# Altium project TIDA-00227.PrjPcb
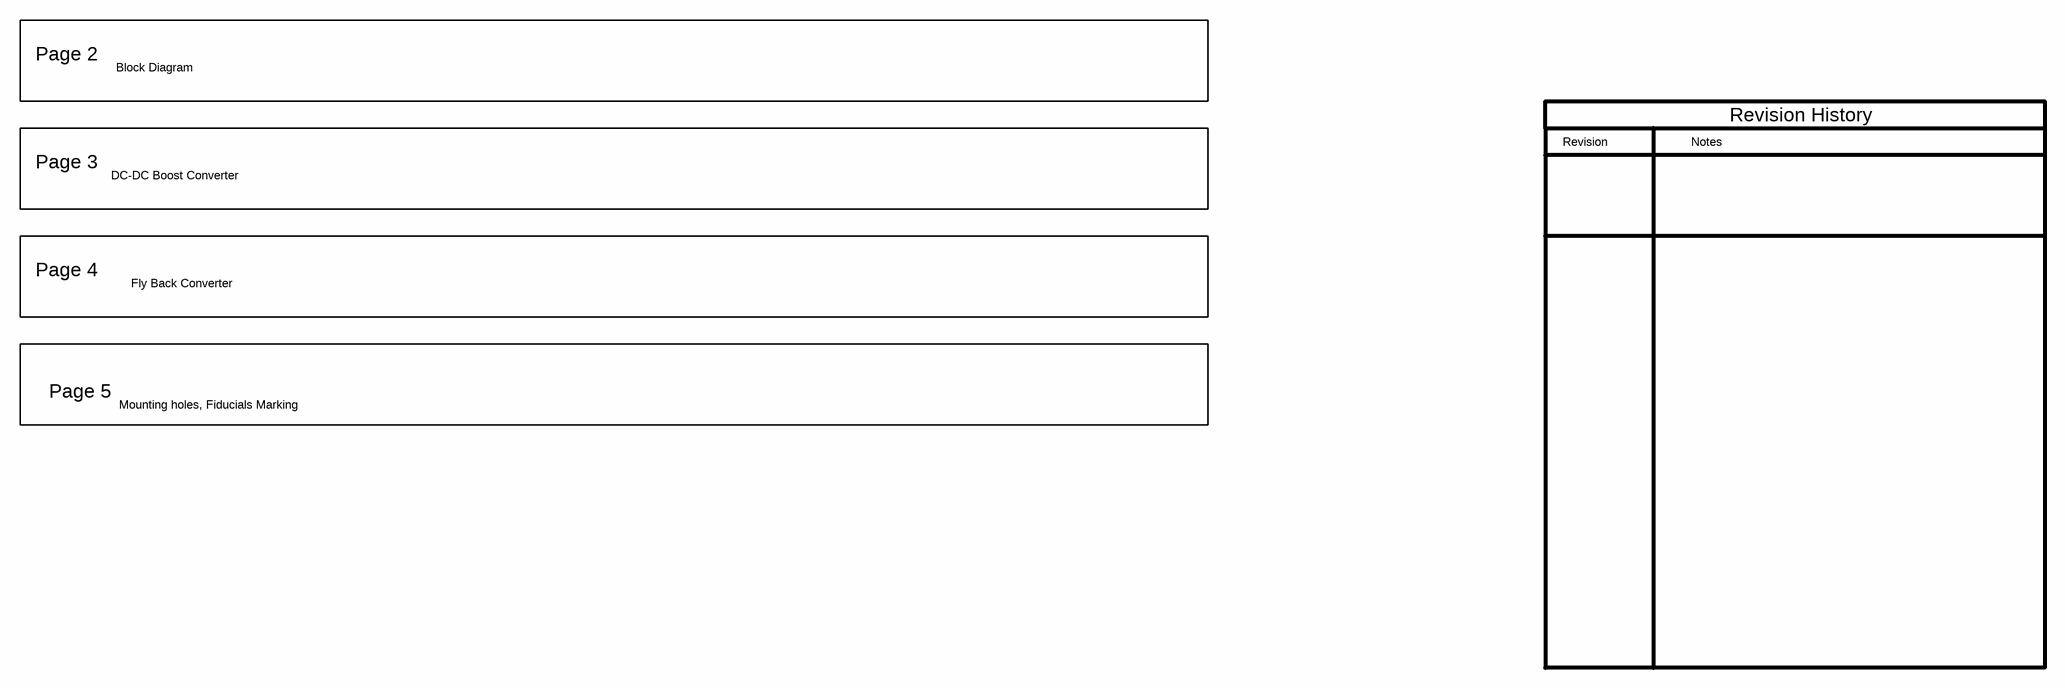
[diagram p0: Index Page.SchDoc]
CopyrightYear: 2014; PCB_Rev: A1; PRJ_Customer: Public Release; PRJ_Engineer: Sunil Dwivedi; PRJ_Number: TIDA-00227; PRJ_Title: TIDA-00227 - ISE3033; SCH_Rev: A1; TechSupport: http://www.ti.com/support
5 sheets, 146 parts. Net scope: flat (ports and power ports of the same name join across sheets).
Board file: TIDA-00227.PcbDoc
Sheets:
  Index Page.SchDoc
  Block Diagram.SchDoc
  Boost converter.SchDoc
  Fly back converter.SchDoc
  Hardware.SchDoc

## Sheet Index Page.SchDoc: Index Page
size 431 x 279 mm; Date: Not shown in title block; ApprovedBy: Not shown in title block; CheckedBy: Not shown in title block; Author: Not shown in title block; CompanyName: Not shown in title block; Engineer: Not shown in title block; Organization: Not shown in title block; Address1: Not shown in title block; Address2: Not shown in title block; Address3: Not shown in title block; Address4: Not shown in title block; DocumentNumber: 1; Revision: Use project parameter SCH_Rev; SheetNumber: 1; SheetTotal: 5; PageSetup: Record=PageOptions|CenterHorizontal=True|CenterVertical=True|PrintScale=1.00|XCorrection=1.00|YCorrection=1.00|PrintKind=0|BorderSize=5000000|LeftOffset=0|BottomOffset=0|Orientation=2|PaperLength=1000|PaperWidth=1000|Scale=100|PaperSource=15|PrintQuality=600|MediaType=1|DitherType=10|PaperKind=Letter|PrintScaleMode=1

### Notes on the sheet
- Page 2
- Block Diagram
- Page 3
- Revision
- Notes
- Revision History
- DC-DC Boost Converter
- Page 4
- Fly Back Converter
- Page 5
- Mounting holes, Fiducials Marking

## Sheet Block Diagram.SchDoc: Block Diagram
size 431 x 279 mm; Date: Not shown in title block; ApprovedBy: Not shown in title block; CheckedBy: Not shown in title block; Author: Not shown in title block; CompanyName: Not shown in title block; Engineer: Not shown in title block; Organization: Not shown in title block; Address1: Not shown in title block; Address2: Not shown in title block; Address3: Not shown in title block; Address4: Not shown in title block; DocumentNumber: 2; Revision: Use project parameter SCH_Rev; SheetNumber: 2; SheetTotal: 5; PageSetup: Record=PageOptions|CenterHorizontal=True|CenterVertical=True|PrintScale=0.96|XCorrection=1.00|YCorrection=1.00|PrintKind=0|BorderSize=5000000|LeftOffset=0|BottomOffset=0|Orientation=2|PaperLength=1000|PaperWidth=1000|Scale=100|PaperSource=15|PrintQuality=600|MediaType=1|DitherType=10|PaperKind=A3|PrintScaleMode=1
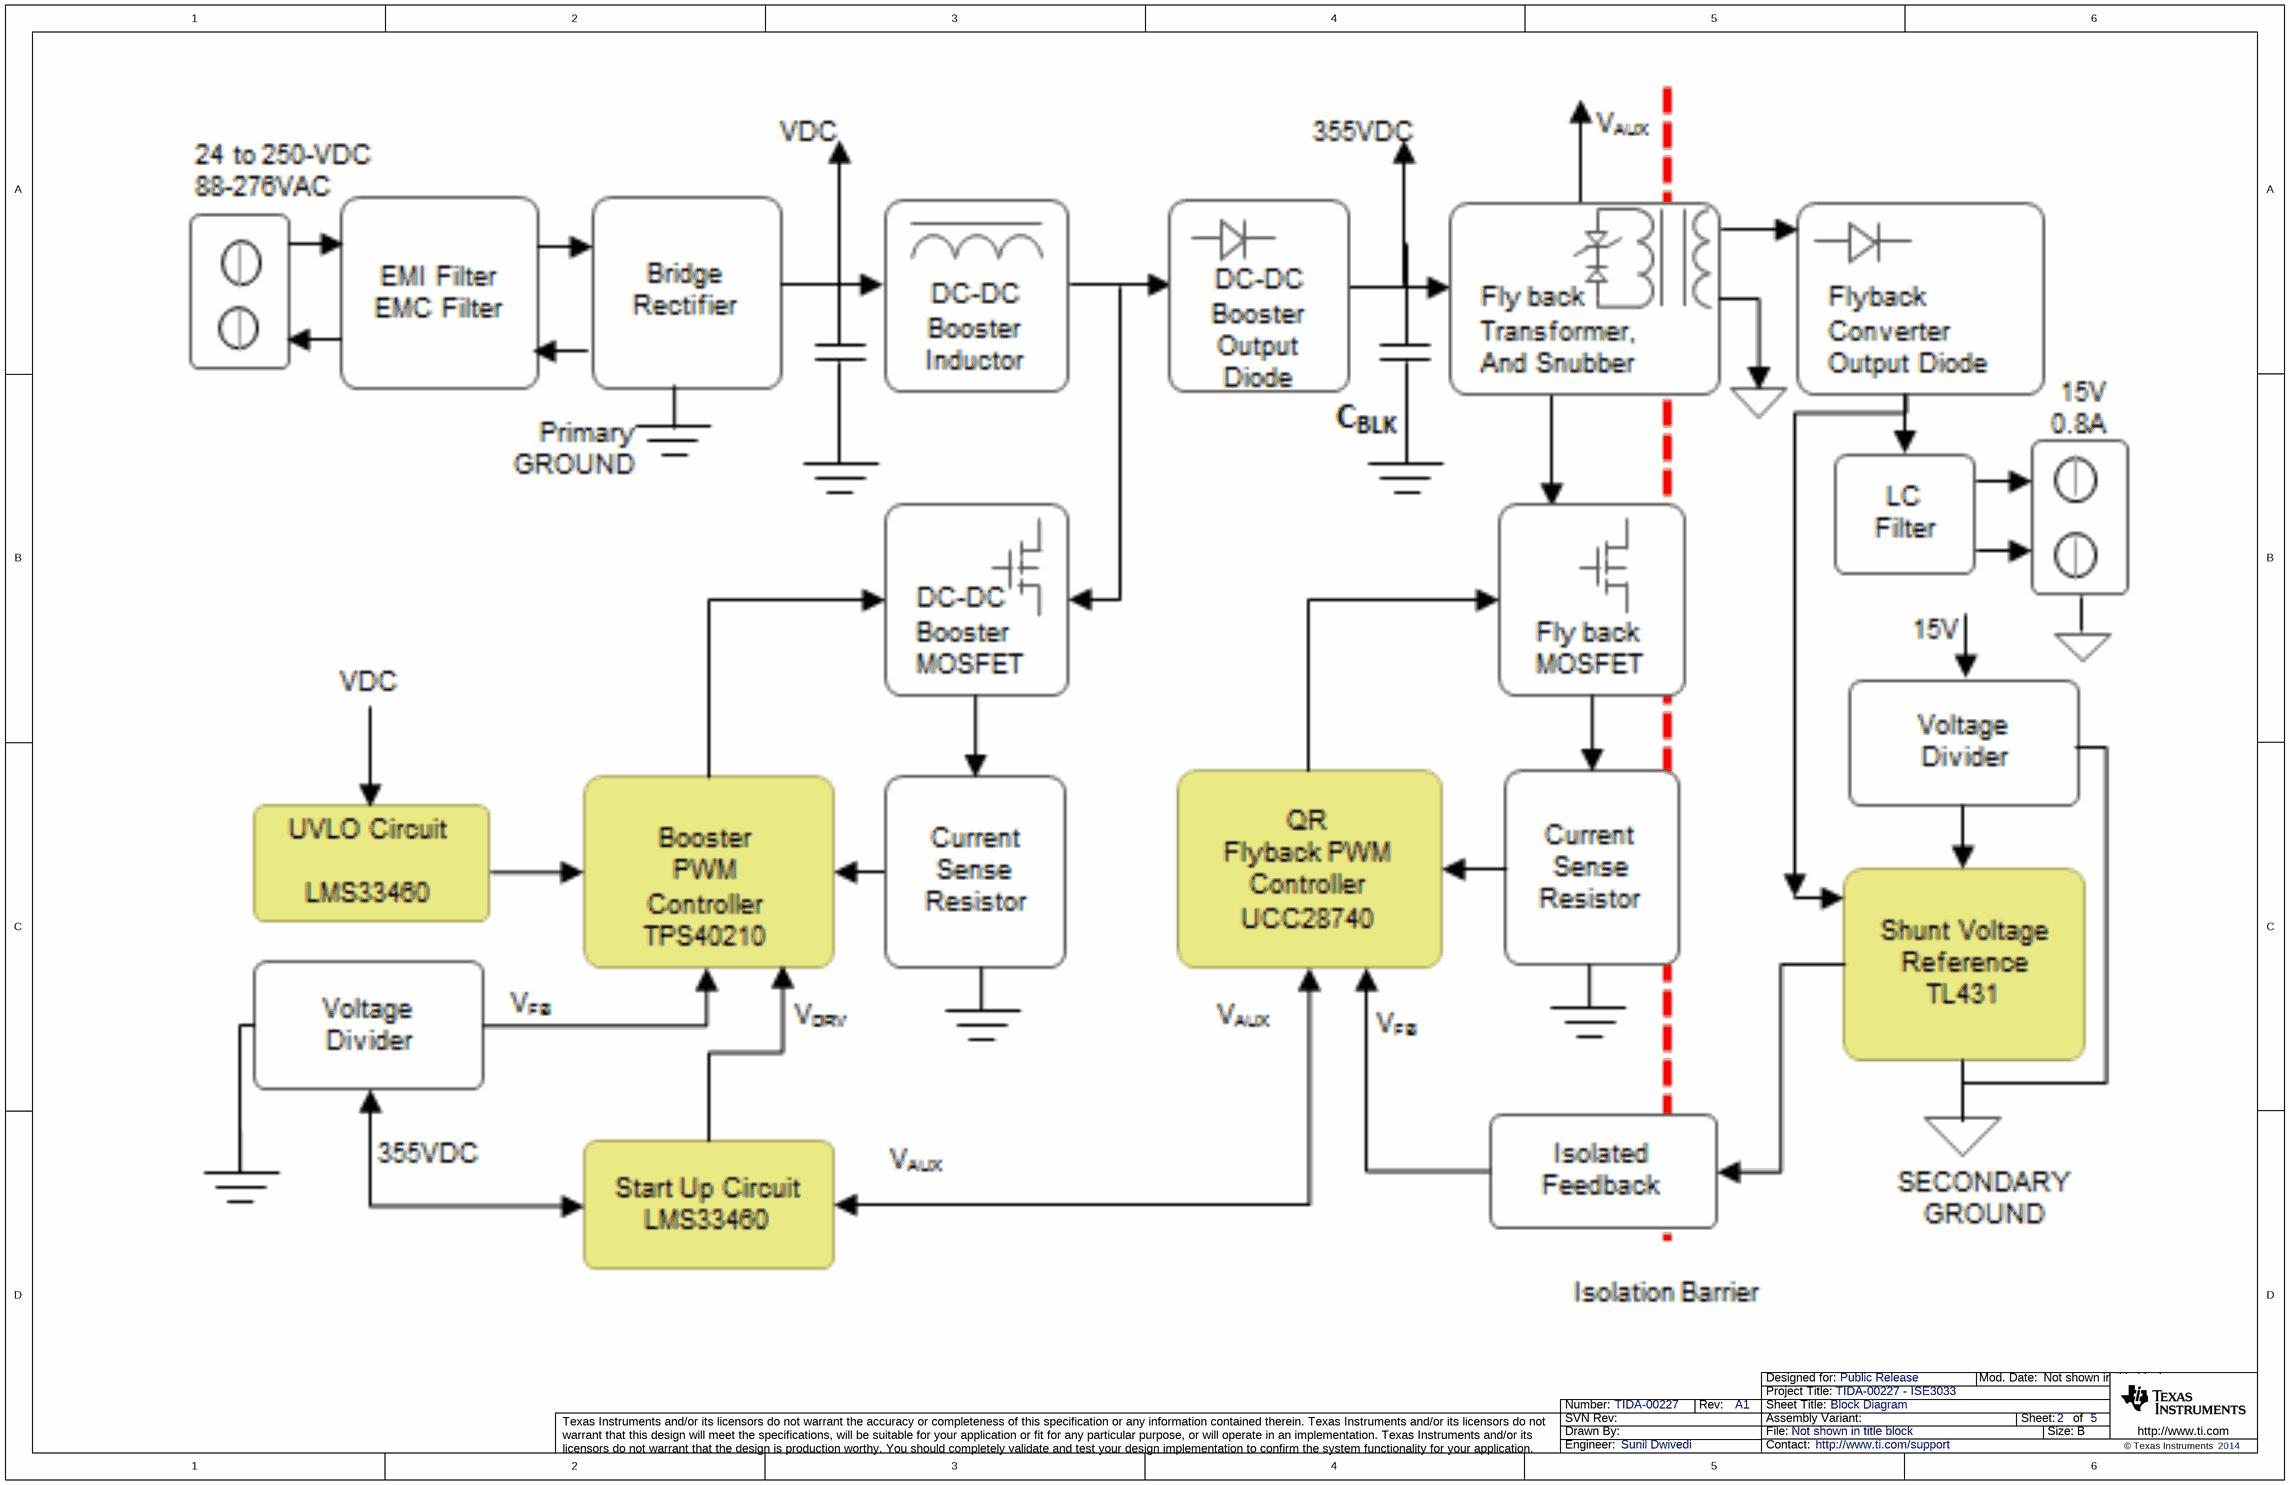
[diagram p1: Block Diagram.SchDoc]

## Sheet Boost converter.SchDoc: DC-DC Boost Converter
size 431 x 279 mm; Date: Not shown in title block; ApprovedBy: Not shown in title block; CheckedBy: Not shown in title block; Author: Not shown in title block; CompanyName: Not shown in title block; Engineer: Not shown in title block; Organization: Not shown in title block; Address1: Not shown in title block; Address2: Not shown in title block; Address3: Not shown in title block; Address4: Not shown in title block; DocumentNumber: 3; Revision: Use project parameter SCH_Rev; SheetNumber: 3; SheetTotal: 5; PageSetup: Record=PageOptions|CenterHorizontal=True|CenterVertical=True|PrintScale=1.00|XCorrection=1.00|YCorrection=1.00|PrintKind=0|BorderSize=5000000|LeftOffset=0|BottomOffset=0|Orientation=2|PaperLength=1000|PaperWidth=1000|Scale=100|PaperSource=15|PrintQuality=600|MediaType=1|DitherType=10|PaperKind=Letter|PrintScaleMode=1
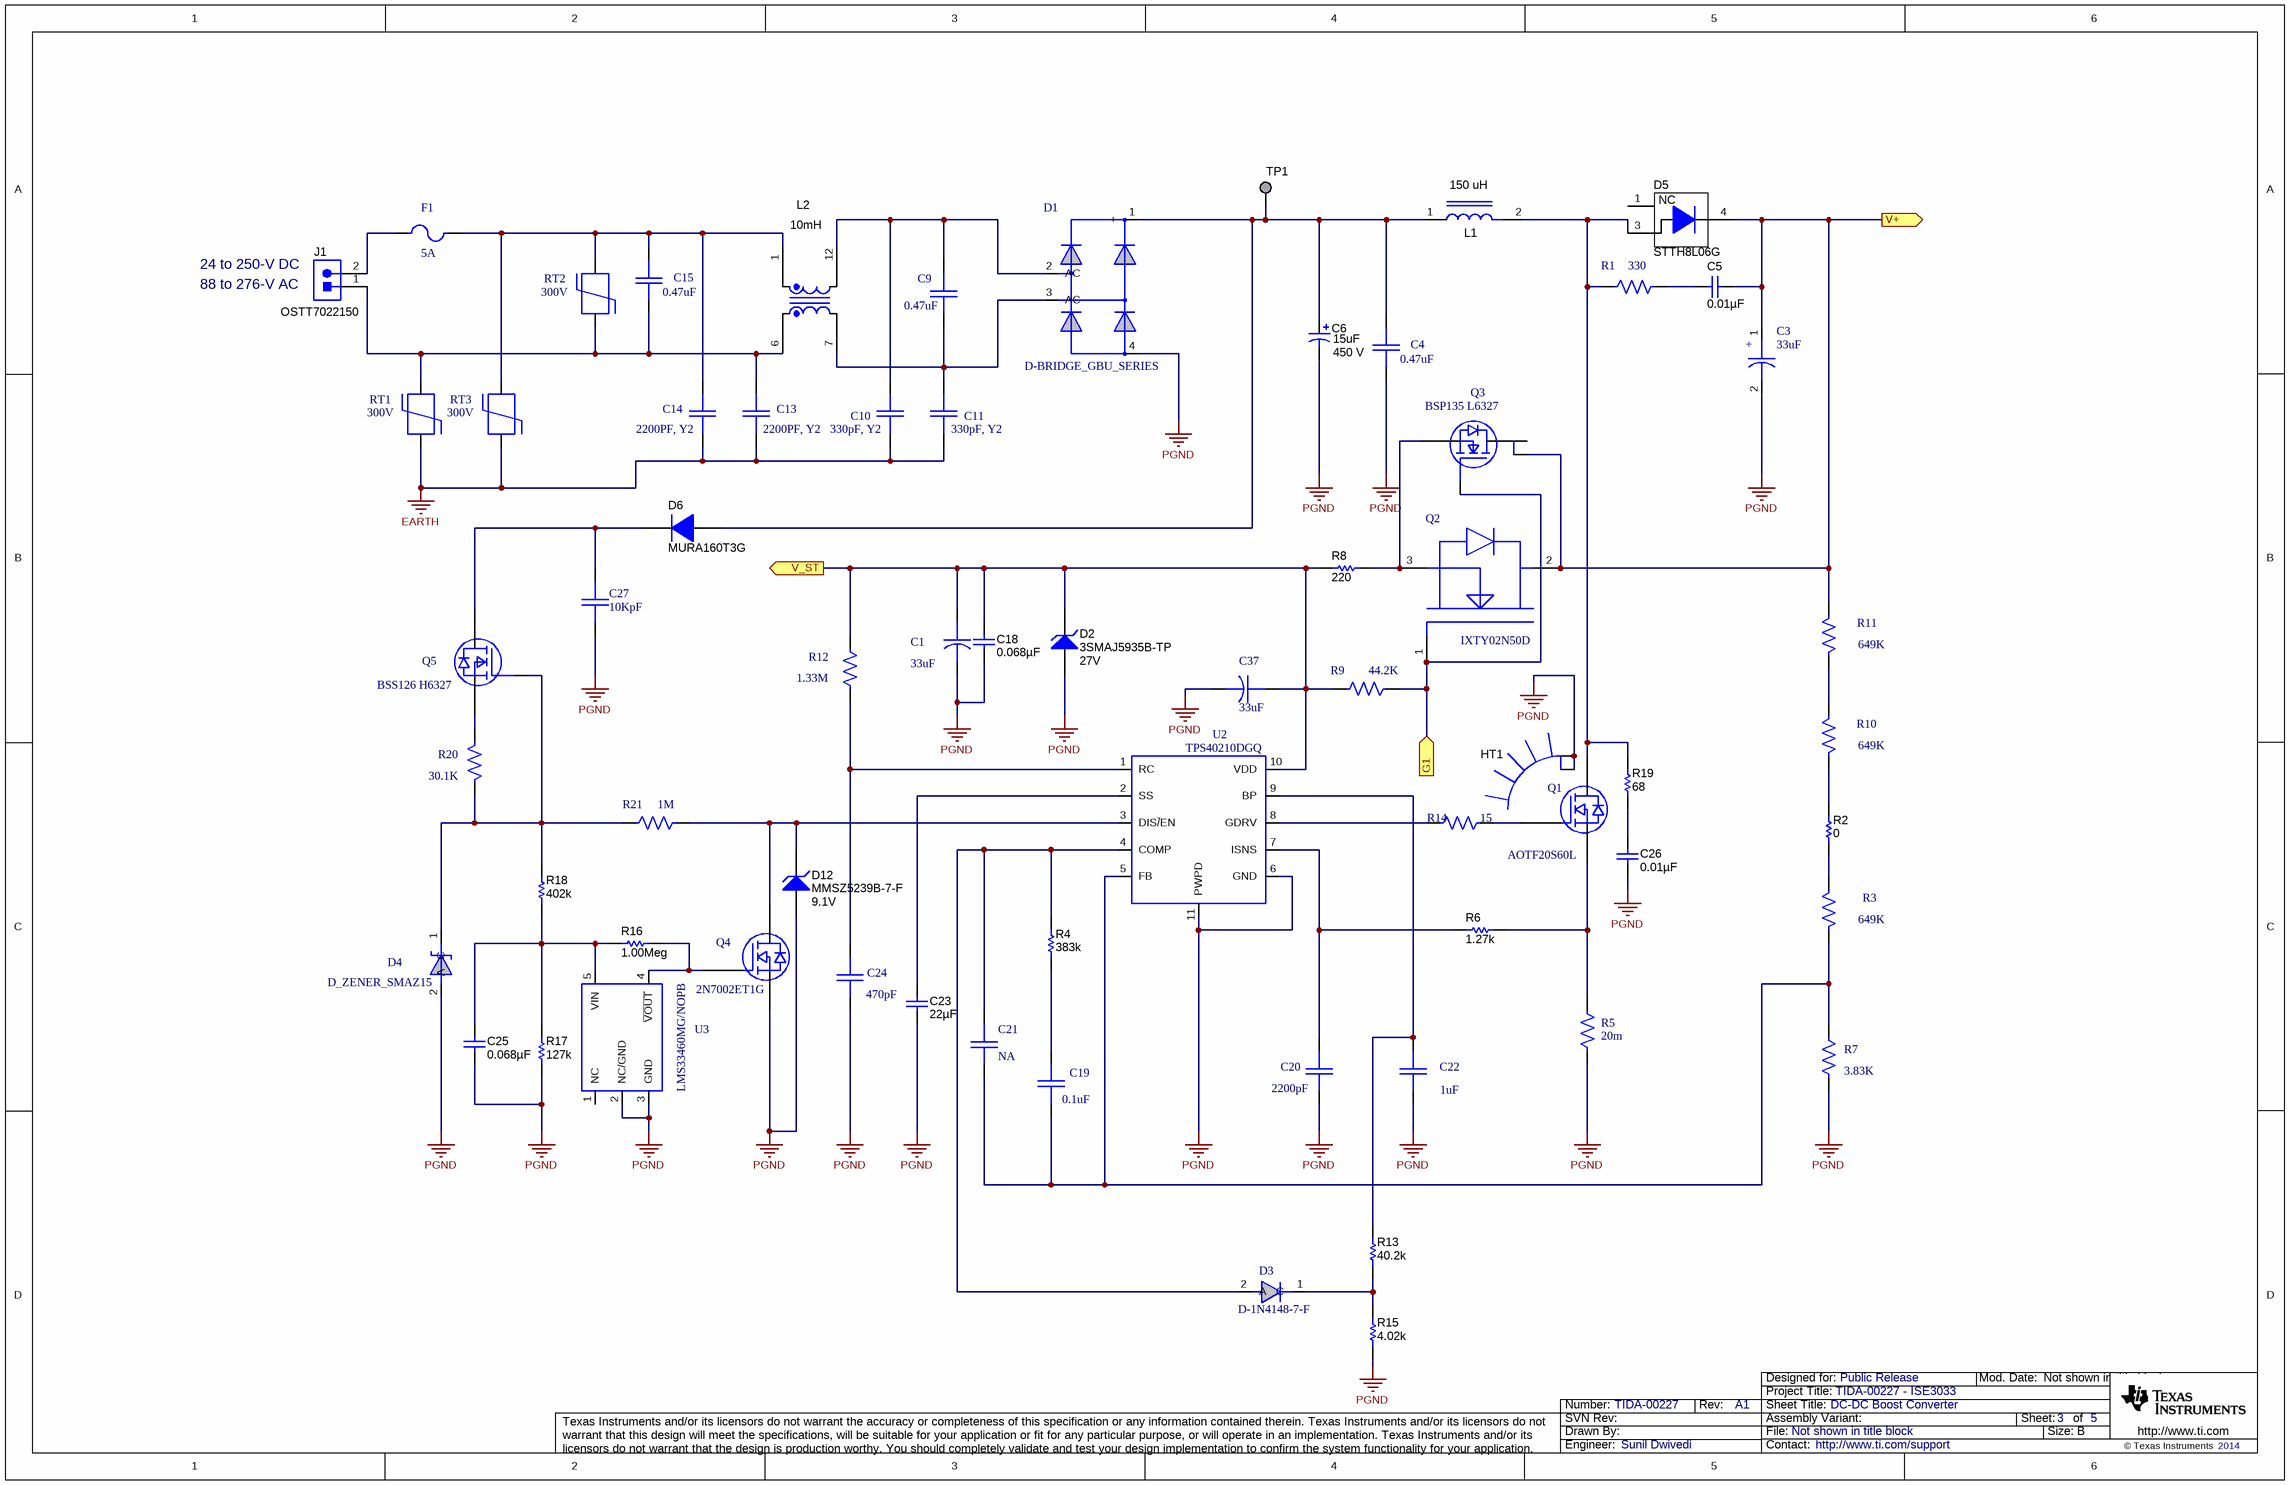
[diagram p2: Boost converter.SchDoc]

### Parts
C1  value 33uF  [CAP_ZL-6.3MM]  (hidden comment: CAP_ZL_6.3MM_SERIES)
C3  33uF  [CAP_EEUFC1H]
C4  value 0.47uF  [CAP_591MIL]  (hidden comment: R46KI347050P1M)
C5  ValueDisplayed: 0.01µF  [1210]  (hidden comment: GRM32QR73A103KW01L)
C6  value 15uF  VDC_V: 450 V  [CAPPR5-12.5X20]  (hidden comment: EEU-EE2W150)
C9  value 0.47uF  [CAP_591MIL]  (hidden comment: R46KI347050P1M)
C10  value 330pF, Y2  [CAP_DISK_8.4MM]  (hidden comment: CAP_DISK_440_[8.4MM])
C11  value 330pF, Y2  [CAP_DISK_8.4MM]  (hidden comment: CAP_DISK_440_[8.4MM])
C13  value 2200PF, Y2  [CAP_DISK_8.4MM]  (hidden comment: VY2222M35Y5US63V7)
C14  value 2200PF, Y2  [CAP_DISK_8.4MM]  (hidden comment: VY2222M35Y5US63V7)
C15  value 0.47uF  [CAP_591MIL]  (hidden comment: R46KI347050P1M)
C18  ValueDisplayed: 0.068µF  [0603]  (hidden comment: GRM188R71H683KA93D)
C19  value 0.1uF  [C603]  (hidden comment: C603)
C20  value 2200pF  [C603]  (hidden comment: C603)
C21  value NA  [C603]  (hidden comment: C603)
C22  value 1uF  [C603]  (hidden comment: C603)
C23  ValueDisplayed: 22µF  [0805_HV]  (hidden comment: C2012X5R1C226K125AC)
C24  value 470pF  [C603]  (hidden comment: C603)
C25  ValueDisplayed: 0.068µF  [0603]  (hidden comment: GRM188R71H683KA93D)
C26  ValueDisplayed: 0.01µF  [1210]  (hidden comment: GRM32QR73A103KW01L)
C27  value 10KpF  [C1812]  (hidden comment: C4532CH2J103K160KA)
C37  value 33uF  [CAP_ZL-6.3MM]  (hidden comment: CAP_ZL_6.3MM_SERIES)
D1  D-BRIDGE_GBU_SERIES  [BRIDGE-INLINE-210-C]
D2  3SMAJ5935B-TP  value 27V  [SMA]
D3  D-1N4148-7-F  [D_SOD123]
D4  D_ZENER_SMAZ15  [DIODE_SMA]
D5  STTH8L06G  [DDPAK]
D6  MURA160T3G  [SMA]
D12  MMSZ5239B-7-F  value 9.1V  [SOD-123]
F1  value 5A  [FUSE_4X8.5-5.08P]  (hidden comment: FUSE_RST_SERIES)
HT1  HEATSINK_513102B02500G  [HEATSINK_513201]  (value not drawn)
J1  OSTT7022150  [TERM_BLK_OSTT7022150]
L1  150 uH  [IND_AIRD-06-151K]
L2  ValueDisplayed: 10mH  [WE-CMB_XL]  (hidden comment: 744825510)
Q1  value AOTF20S60L  [TO-220V]  (hidden comment: TR-FQPF2N60C)
Q2  IXTY02N50D  [TO228P991X238-3N]
Q3  value BSP135 L6327  [TR_SOT223]  (hidden comment: TR_NFET_SOT223)
Q4  value 2N7002ET1G  [SOT-23]  (hidden comment: TR-2N7002)
Q5  value BSS126 H6327  [SOT-23]  (hidden comment: TR-BSS126)
R1  value 330  [R2512]  (hidden comment: R2512)
R2  value 0  [1206]  (hidden comment: RC1206JR-070RL)
R3  value 649K  [r1206]  (hidden comment: R1206)
R4  value 383k  [0603]  (hidden comment: CRCW0603383KFKEA)
R5  value 20m  [R2512]  (hidden comment: R2512_1%)
R6  value 1.27k  [0603]  (hidden comment: CRCW06031K27FKEA)
R7  value 3.83K  [R603]  (hidden comment: R603)
R8  value 220  [0603]  (hidden comment: RC0603FR-07220RL)
R9  value 44.2K  [R603]  (hidden comment: R603)
R10  value 649K  [R1206]  (hidden comment: R1206)
R11  value 649K  [R1206]  (hidden comment: R1206)
R12  value 1.33M  [R603]  (hidden comment: R603)
R13  value 40.2k  [0603]  (hidden comment: CRCW060340K2FKEA)
R14  value 15  [R0805]  (hidden comment: R0805_1%)
R15  value 4.02k  [0603]  (hidden comment: RC0603FR-074K02L)
R16  value 1.00Meg  [0603]  (hidden comment: CRCW06031M00FKEA)
R17  value 127k  [0603]  (hidden comment: CRCW0603127KFKEA)
R18  value 402k  [0603]  (hidden comment: CRCW0603402KFKEA)
R19  value 68  [2512M]  (hidden comment: RHC2512FT68R0)
R20  value 30.1K  [R603]  (hidden comment: R603)
R21  value 1M  [R603]  (hidden comment: R603)
RT1  value 300V  [DISK-472]  (hidden comment: MOV_B72210SXXXXK101)
RT2  value 300V  [DISK-472]  (hidden comment: MOV_B72210SXXXXK101)
RT3  value 300V  [DISK-472]  (hidden comment: MOV_B72210SXXXXK101)
TP1  TESTPOINT  [TESTPOINT]  (value not drawn)  (no BOM)
U2  TPS40210DGQ  [DGQ_10PWP]
U3  value LMS33460MG/NOPB  [SC-70-5]  (hidden comment: LMS33460)

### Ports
G1, V+, V_ST

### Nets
EARTH: C10.2 C11.2 C13.2 C14.2 RT1.1 RT3.1
PGND: C1.2 C3.2 C4.1 C6.2(-) C18.2 C20.1 C22.1 C23.2 C24.1 C25.2 C26.2 C27.1 C37.2 D1.4(-) D2.2(A) D4.2(A) D12.2(A) HT1.1 HT1.2 Q4.2(S) R5.2 R7.2 R15.1 R17.2 U2.6(GND) U2.11(PWPD) U3.2(NC/GND) U3.3(GND)
NetC1_1: C1.1 C18.1 C37.1 D2.1(K) R8.1 R9.2 R12.1 U2.10(VDD) ; port V_ST
NetC2_2: C3.1 C5.2 D5.4(K) Q2.2(D) Q3.4(D) R11.1 ; port V+
NetC4_2: C4.2 C6.1(+) D1.1(+) D6.2(A) L1.1 TP1.1
NetC5_1: C5.1 R1.2
NetC9_1: C9.1 C11.1 D1.3(AC) L2.7
NetC9_2: C9.2 C10.1 D1.2(AC) L2.12
NetC13_1: C13.1 C15.1 J1.1 L2.6 RT1.2 RT2.1
NetC14_1: C14.1 C15.2 F1.2 L2.1 RT2.2 RT3.2
NetC19_1: C19.1 R4.2
NetC19_2: C19.2 C21.1 R3.2 R7.1 U2.5(FB)
NetC20_2: C20.2 R6.1 U2.7(ISNS)
NetC21_2: C21.2 D3.2(A) R4.1 U2.4(COMP)
NetC22_2: C22.2 R13.2 U2.9(BP)
NetC23_1: C23.1 U2.2(SS)
NetC24_2: C24.2 R12.2 U2.1(RC)
NetC25_1: C25.1 R16.1 R17.1 R18.2 U3.5(VIN)
NetC26_1: C26.1 R19.1
NetC27_2: C27.2 D6.1(K) Q5.3(D)
NetD3_1: D3.1(C) R13.1 R15.2
NetD4_1: D4.1(C) Q5.1(G) R18.1 R20.2 R21.1
NetD5_3: D5.3(A) L1.2 Q1.2(D) R1.1 R19.2
NetD12_1: D12.1(K) Q4.3(D) R21.2 U2.3(DIS~{/}EN)
NetF1_1: F1.1 J1.2
NetQ1_1: Q1.1(G) R14.2
NetQ1_3: Q1.3(S) R5.1 R6.2
NetQ2_1: Q2.1(G) Q3.1(G) R9.1 ; port G1
NetQ2_3: Q2.3(S) Q3.3(S) R8.2
NetQ4_1: Q4.1(G) R16.2 U3.4(~{VOUT})
NetQ5_2: Q5.2(S) R20.1
NetR2_1: R2.1 R3.1
NetR2_2: R2.2 R10.2
NetR10_1: R10.1 R11.2
NetR14_1: R14.1 U2.8(GDRV)

Not connected (* = marked no-connect by the designer): D5 1(NC); Q3 2(D); U3 1(NC)

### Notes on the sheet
- (near J1) 24 to 250-V DC
- (near J1) 88 to 276-V AC

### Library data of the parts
C1 C37 = CAP_ZL_6.3MM_SERIES: CAP ALUM 33UF 35V 20% RADIAL; Manufacturer: Rubycon; PartNumber: 35YXJ33M5X11; Area: 70,686; Type: CAP_ZL_6.3MM SERIES
C3 = CAP_KXG-18X25MM_HORIZ_SERIES: CAP ALUM 33UF 450V 20% RADIAL; PartNumber: EKXG451ELL330MM20S; Manufacturer: Nippon; Area: 667.40 mm; Value: 33uH
C4 C9 C15 = CAP_ECQU2A104XL: CAP FILM 0.47UF 560VDC RADIAL; Manufacturer: Kemet; PCB DECAL: 18.00mm x 9.00mm; Area: 97500
C5 C26 = GRM32QR73A103KW01L: CAP, CERM, 0.01uF, 1000V, +/-10%, X7R, 1210; Manufacturer: MuRata; Polarized: N; CompType: Capacitor; U/M: EA; Cap_F: 0.00000001; Tolerance_%: 10; Value1: Unknown; VDC_V: 1000; TaMin_C: -55; TaMax_C: 125
C6 = EEUED2W100: CAP ALUM 15UF 450V 20% RADIAL; Manufacturer: Panasonic; Polarized: Y; CompType: Capacitor; U/M: EA; Cap_F: 0.00001; Tolerance_%: 20; TaMin_C: -25; TaMax_C: 105; AC_Derating: 0.3
C10 C11 = CAP_DISK_440_[8.4MM]: CAP CER 330PF 300VAC 10% RADIAL; Manufacturer: Vishay; Part_Number: VY2331K29Y5SS63V7; PartNumber: Part Number; Description: Capacitor, 300VAC, X1Y2, ±10%; Area: 103.50 mm; Reference: \\vette02\pmp_pcb\pcad_pdf's\440l.pdf; Second_Source: C:\program files\p-cad 2004\pcad_pdf's\ABB0000CE12.pdf; Type: CAP_DISK_720; Second Source: C:\program files\p-cad2004pcad_pdf's\440l.pdf
C13 C14 = CAP_DISK_440_[8.4MM]: CAP CER 2200PF 300VAC 20% RADIAL; Manufacturer: Vishay
C18 C25 = GRM188R71H683KA93D: CAP, CERM, 0.068uF, 50V, +/-10%, X7R, 0603; Manufacturer: MuRata; Polarized: N; CompType: Capacitor; U/M: EA; Cap_F: 0.000000068; Tolerance_%: 10; Value1: Unknown; VDC_V: 50; TaMin_C: -55; TaMax_C: 125
C19 = C603: CAP CER 0.1UF 50V 10% X7R 0603; Manufacturer: Kemet; PartNumber: C0603C104K5RACTU; Area: 5650
C20 = C603: CAP, CERM, 2200pF, 50V, +/-10%, X7R, 0603; Manufacturer: Kemet; Part_Number: Std; PartNumber: C0603C222K5RAC; Area: 5650
C21 C24 = C603: CAP CER 470PF 50V 5% NP0 0603; Manufacturer: AVX Corporation; PartNumber: 06035A471JAT2A; Area: 5650
C22 = C603: CAP CER 1UF 25V 10% X7R 0603; Manufacturer: Kemet; PartNumber: C0603C105K3RACTU; Area: 5650
C23 = C2012X5R1C226K125AC: CAP, CERM, 22uF, 16V, +/-10%, X5R, 0805; Manufacturer: TDK; Polarized: N; CompType: Capacitor; U/M: EA; Cap_F: 0.000022; Tolerance_%: 10; Value1: Unknown; VDC_V: 16; TaMin_C: -55; TaMax_C: 85; Cap_Case: 0805
C27 = C1812: Corporation CAP CER 10000PF 630V 10% CH 1812; Manufacturer: TDK Corporation; Area: 43,360
D1 = D-BRIDGE_GBU_SERIES: RECT BRIDGE GPP 8A 600V GBU; PartNumber: GBU8J-BPMS; Manufacturer: Micro Commercial Co; Area: 163800; Value: GBU8J-BPMS
D2 = 3SMAJ5935B-TP: Diode, Zener, 27V, 3W, SMA; Manufacturer: Micro Commercial Components; SymbolCreator: a0412235; U/M: EA; Power_W: 3; Vz_V: 27; RJA_CperW: 226
D3 = D-1N4148-7-F: Diode, Signal, 300-mA, 75-V, 350-mW; PartNumber: 1N4148W-7-F; Manufacturer: Diodes; Area: 13300; Value: 1N4148W-7-F
D4 = D_ZENER_SMAZ15: Diode, Zener,15-V, 1W; PartNumber: SMAZ15; Manufacturer: Diodes; Area: 37520; Value: SMAZ15
D5 = STTH8L06G: Diode, Ultrafast, 600V, 8A, DDPAK; Manufacturer: ST Microelectronics; SymbolCreator: a0412235; U/M: EA; Vf_V: 0.0875; Value2: 0.0875V; Io_A: 8; Vr_V: 600; TJmax_C: 175; RJC_CperW: 2.5
D6 = MURA160T3G: Diode, Ultrafast, 600V, 1A, SMA; Manufacturer: ON Semiconductor; U/M: EA; Vf_V: 1.05; Value2: 1.05V; Io_A: 1; Vr_V: 600; TJmax_C: 175
D12 = MMSZ5239B-7-F: Diode, Zener, 9.1V, 500mW, SOD-123; Manufacturer: Diodes Inc.; SymbolCreator: a0412235; U/M: EA; Power_W: 0.5; Vz_V: 9.1; Value1: 0.5W; RJA_CperW: 350
F1 = FUSE_RST_SERIES: FUSE SLOW 250VAC 5A RADIAL; Manufacturer: BEL; PartNumber: RST 5; Area: 43.2 mm; Reference: \\vette02\pmp_pcb\pcad_pdf's\RST.pdf; Second Source: C:\program files\p-cad 2004\pcad_pdf's\RST.pdf
HT1 = HEATSINK_513201: HEATSINK TO-220 W/PINS 1.5"TALL; Manufacturer: Aavid Thermalloy; area: 739800
J1 = OSTT7022150: Terminal Block, 30A, 9.52mm (.375) Pitch, 2-Pos, TH; Manufacturer: On-Shore Technology; SymbolCreator: a0412235; CompType: Connector; U/M: EA
L1 = IND_AIRD-06-151K: INDUCTOR 150UH 4.0A 10%; Manufacturer: Abracon Corporation; Area: 113411
L2 = 744825510: Coupled inductor, 10mH, 5A, 0.055 ohm, TH; Manufacturer: Wurth Elektronik eiSos; SymbolCreator: a0799628; Ind_H: 10.0E-3; DCR_ohm: 0.055; Isat: 5
Q1 = TR-FQPF2N60C: MOSFET, Nch, 600-V, 20A, 0.199 Ohms; Manufacturer: Alpha&Omega; Area: 65.4 mm; Reference: \\vette02\pmp_pcb\pcad_pdf's\FQPF2N60C.pdf; Second Source: C:\program files\p-cad 2004\pcad_pdf's\FQPF2N60C.pdf
Q2 = IXTY02N50D: DISCRETE, MOSFET N-CH 500V 200MA, DPAK; Manufacturer: IXYS; SymbolCreator: x0199378
Q3 = TR_NFET_SOT223: MOSFET N-CH 600V 120MA SOT-223; Manufacturer: Infineon; Second Source: C:\program files\p-cad 2004\pcad_pdf's\BSS126.pdf; Reference: \\vette02\pmp_pcb\pcad_pdf's\BSS126.pdf; Area: 86400
Q4 = TR-2N7002: MOSFET N-CH 60V 260MA SOT-23; Manufacturer: OnSemi; Second Source: C:\program files\p-cad 2004\pcad_pdf's\Diodes_2n7002.pdf; Reference: \\vette02\pmp_pcb\pcad_pdf's\Diodes_2n7002.pdf; Area: 14105
Q5 = TR-BSS126: MOSFET N-CH 600V 21MA SOT23; Manufacturer: Infineon; Second Source: C:\program files\p-cad 2004\pcad_pdf's\BSS126.pdf; Reference: \\vette02\pmp_pcb\pcad_pdf's\BSS126.pdf; Area: 14105
R1 = R2512: RES 330 OHM 1W 5% 2512; Manufacturer: Samsung; PartNumber: RC6432J331CS; Area: 35100
R2 = RC1206JR-070RL: RES, 0 ohm, 5%, 0.25W, 1206; Manufacturer: Yageo America; CompType: Resistor; Value_Code: 0000; Tolerance_%: 5; Power_W: 0.25; VDC_V: 200; TempCo: 200 ppm/C; EIA_Code: E24; U/M: EA
R3 R10 R11 = R1206: RES 649K OHM 1/4W 1% 1206 SMD; Manufacturer: Yageo; PartNumber: RC1206FR-07649KL; Area: 15390
R4 = CRCW0603383KFKEA: RES, 383k ohm, 1%, 0.1W, 0603; Manufacturer: Vishay-Dale; CompType: Resistor; Res_ohm: 383000; Tolerance_%: 1; Power_W: 0.1; VDC_V: 75; TempCo: 100 ppm/C; EIA_Code: E96; U/M: EA
R5 = R2512_1%: RES 0.02 OHM 1W 1% 2512 SMD; Manufacturer: TT/Welwyn; PartNumber: LRMAM2512-R02FT4; Area: 56000; Second Source: C:\program files\p-cad 2004\pcad_pdf's\SML-LXR1206USBC-TR[1].pdf; Reference: \\vette02\pmp_pcb\pcad_pdf's\SML-LXR1206USBC-TR[1].pdf
R6 = CRCW06031K27FKEA: RES, 1.27k ohm, 1%, 0.1W, 0603; Manufacturer: Vishay-Dale; CompType: Resistor; Res_ohm: 1270; Value_Code: 1k27; Tolerance_%: 1; Power_W: 0.1; VDC_V: 75; TempCo: 100 ppm/C; EIA_Code: E96; U/M: EA
R7 = R603: RES 3.83K OHM 1/10W 1% 0603 SMD; Part_Number: RC0603FR-073K83L; Manufacturer: Yageo; Area: 5650
R8 = RC0603FR-07220RL: RES, 220 ohm, 1%, 0.1W, 0603; Manufacturer: Yageo America; CompType: Resistor; Value_Code: 220R; Tolerance_%: 1; Power_W: 0.1; VDC_V: 150; TempCo: 200 ppm/C; U/M: EA
R9 = R603: RES 44.2K OHM 1/10W 1% 0603 SMD; Part_Number: RC0603FR-0744K2L; Manufacturer: Yageo; Area: 5650
R12 = R603: RES 1.33M OHM 1/10W 1% 0603 SMD; Part_Number: CRCW06031M33FKEA; Manufacturer: Vishay Dale; Area: 5650
R13 = CRCW060340K2FKEA: RES, 40.2k ohm, 1%, 0.1W, 0603; Manufacturer: Vishay-Dale; CompType: Resistor; Res_ohm: 40200; Value_Code: 40k2; Tolerance_%: 1; Power_W: 0.1; VDC_V: 75; TempCo: 100 ppm/C; EIA_Code: E96; U/M: EA
R14 = R0805_1%: RES 15.0 OHM 1/8W 1% 0805 SMD; Part_Number: RC0805FR-0715RL; Manufacturer: Yageo; Area: 15,300
R15 = RC0603FR-074K02L: RES, 4.02k ohm, 1%, 0.1W, 0603; Manufacturer: Yageo America; CompType: Resistor; Res_ohm: 4020; Value_Code: 4k02; Tolerance_%: 1; Power_W: 0.1; VDC_V: 150; TempCo: 200 ppm/C; EIA_Code: E96; U/M: EA
R16 = CRCW06031M00FKEA: RES, 1.00Meg ohm, 1%, 0.1W, 0603; Manufacturer: Vishay-Dale; CompType: Resistor; Res_ohm: 1000000; Value_Code: 1M00; Tolerance_%: 1; Power_W: 0.1; VDC_V: 75; TempCo: 100 ppm/C; EIA_Code: E96; U/M: EA
R17 = CRCW0603127KFKEA: RES, 127k ohm, 1%, 0.1W, 0603; Manufacturer: Vishay-Dale; CompType: Resistor; Res_ohm: 127000; Tolerance_%: 1; Power_W: 0.1; VDC_V: 75; TempCo: 100 ppm/C; EIA_Code: E96; U/M: EA
R18 = CRCW0603402KFKEA: RES, 402k ohm, 1%, 0.1W, 0603; Manufacturer: Vishay-Dale; CompType: Resistor; Res_ohm: 402000; Tolerance_%: 1; Power_W: 0.1; VDC_V: 75; TempCo: 100 ppm/C; EIA_Code: E96; U/M: EA
R19 = CRCW251222R0JNEGHP: RES 68 OHM 2W 1% 2512; Manufacturer: Stackpole Electronics Inc; CompType: Resistor; Tolerance_%: 1
R20 = R603: RES 30.1K OHM 1/10W 1% 0603 SMD; Part_Number: RC0603FR-0730K1L; Manufacturer: Yageo; Area: 5650
R21 = R603: RES 1.00M OHM 1/10W 1% 0603 SMD; Part_Number: RC0603FR-071ML; Manufacturer: Yageo; Area: 5650
RT1-RT3 = MOV_B72210SXXXXK101: MOV, 300V; Manufacturer: Bourns; Part_Number: MOV-10D471KTR; Area: 85,500
TP1 = TESTPOINT: TEST POINT.  No entry in BOM.; PartNumber: Part Number
U2 = TPS40210DGQ: IC REG CTRLR BST FLYBK CM 10MSOP; Manufacturer: TI; PartNumber: TPS40210DGQR; Area: 38400; Reference: \\vette02\pmp_pcb\pcad_pdf's\tps40210.pdf; Second Source: C:\program files\p-cad 2004\pcad_pdf's\tps40210.pdf
U3 = LMS33460: IC DETECTOR UNDER VOLT 3V SC70-5; Manufacturer: TI; Second Source: C:\program files\p-cad 2004\pcad_pdf's\lms33460[1].pdf; Reference: \\vette02\pmp_pcb\pcad_pdf's\lms33460[1].pdf; Area: 12.05 mm

## Sheet Fly back converter.SchDoc: Flyback Converter
size 431 x 279 mm; Date: Not shown in title block; ApprovedBy: Not shown in title block; CheckedBy: Not shown in title block; Author: Not shown in title block; CompanyName: Not shown in title block; Engineer: Not shown in title block; Organization: Not shown in title block; Address1: Not shown in title block; Address2: Not shown in title block; Address3: Not shown in title block; Address4: Not shown in title block; DocumentNumber: 4; Revision: Use project parameter SCH_Rev; SheetNumber: 4; SheetTotal: 5; PageSetup: Record=PageOptions|CenterHorizontal=True|CenterVertical=True|PrintScale=1.00|XCorrection=1.00|YCorrection=1.00|PrintKind=0|BorderSize=5000000|LeftOffset=0|BottomOffset=0|Orientation=2|PaperLength=1000|PaperWidth=1000|Scale=100|PaperSource=15|PrintQuality=600|MediaType=1|DitherType=10|PaperKind=Letter|PrintScaleMode=1
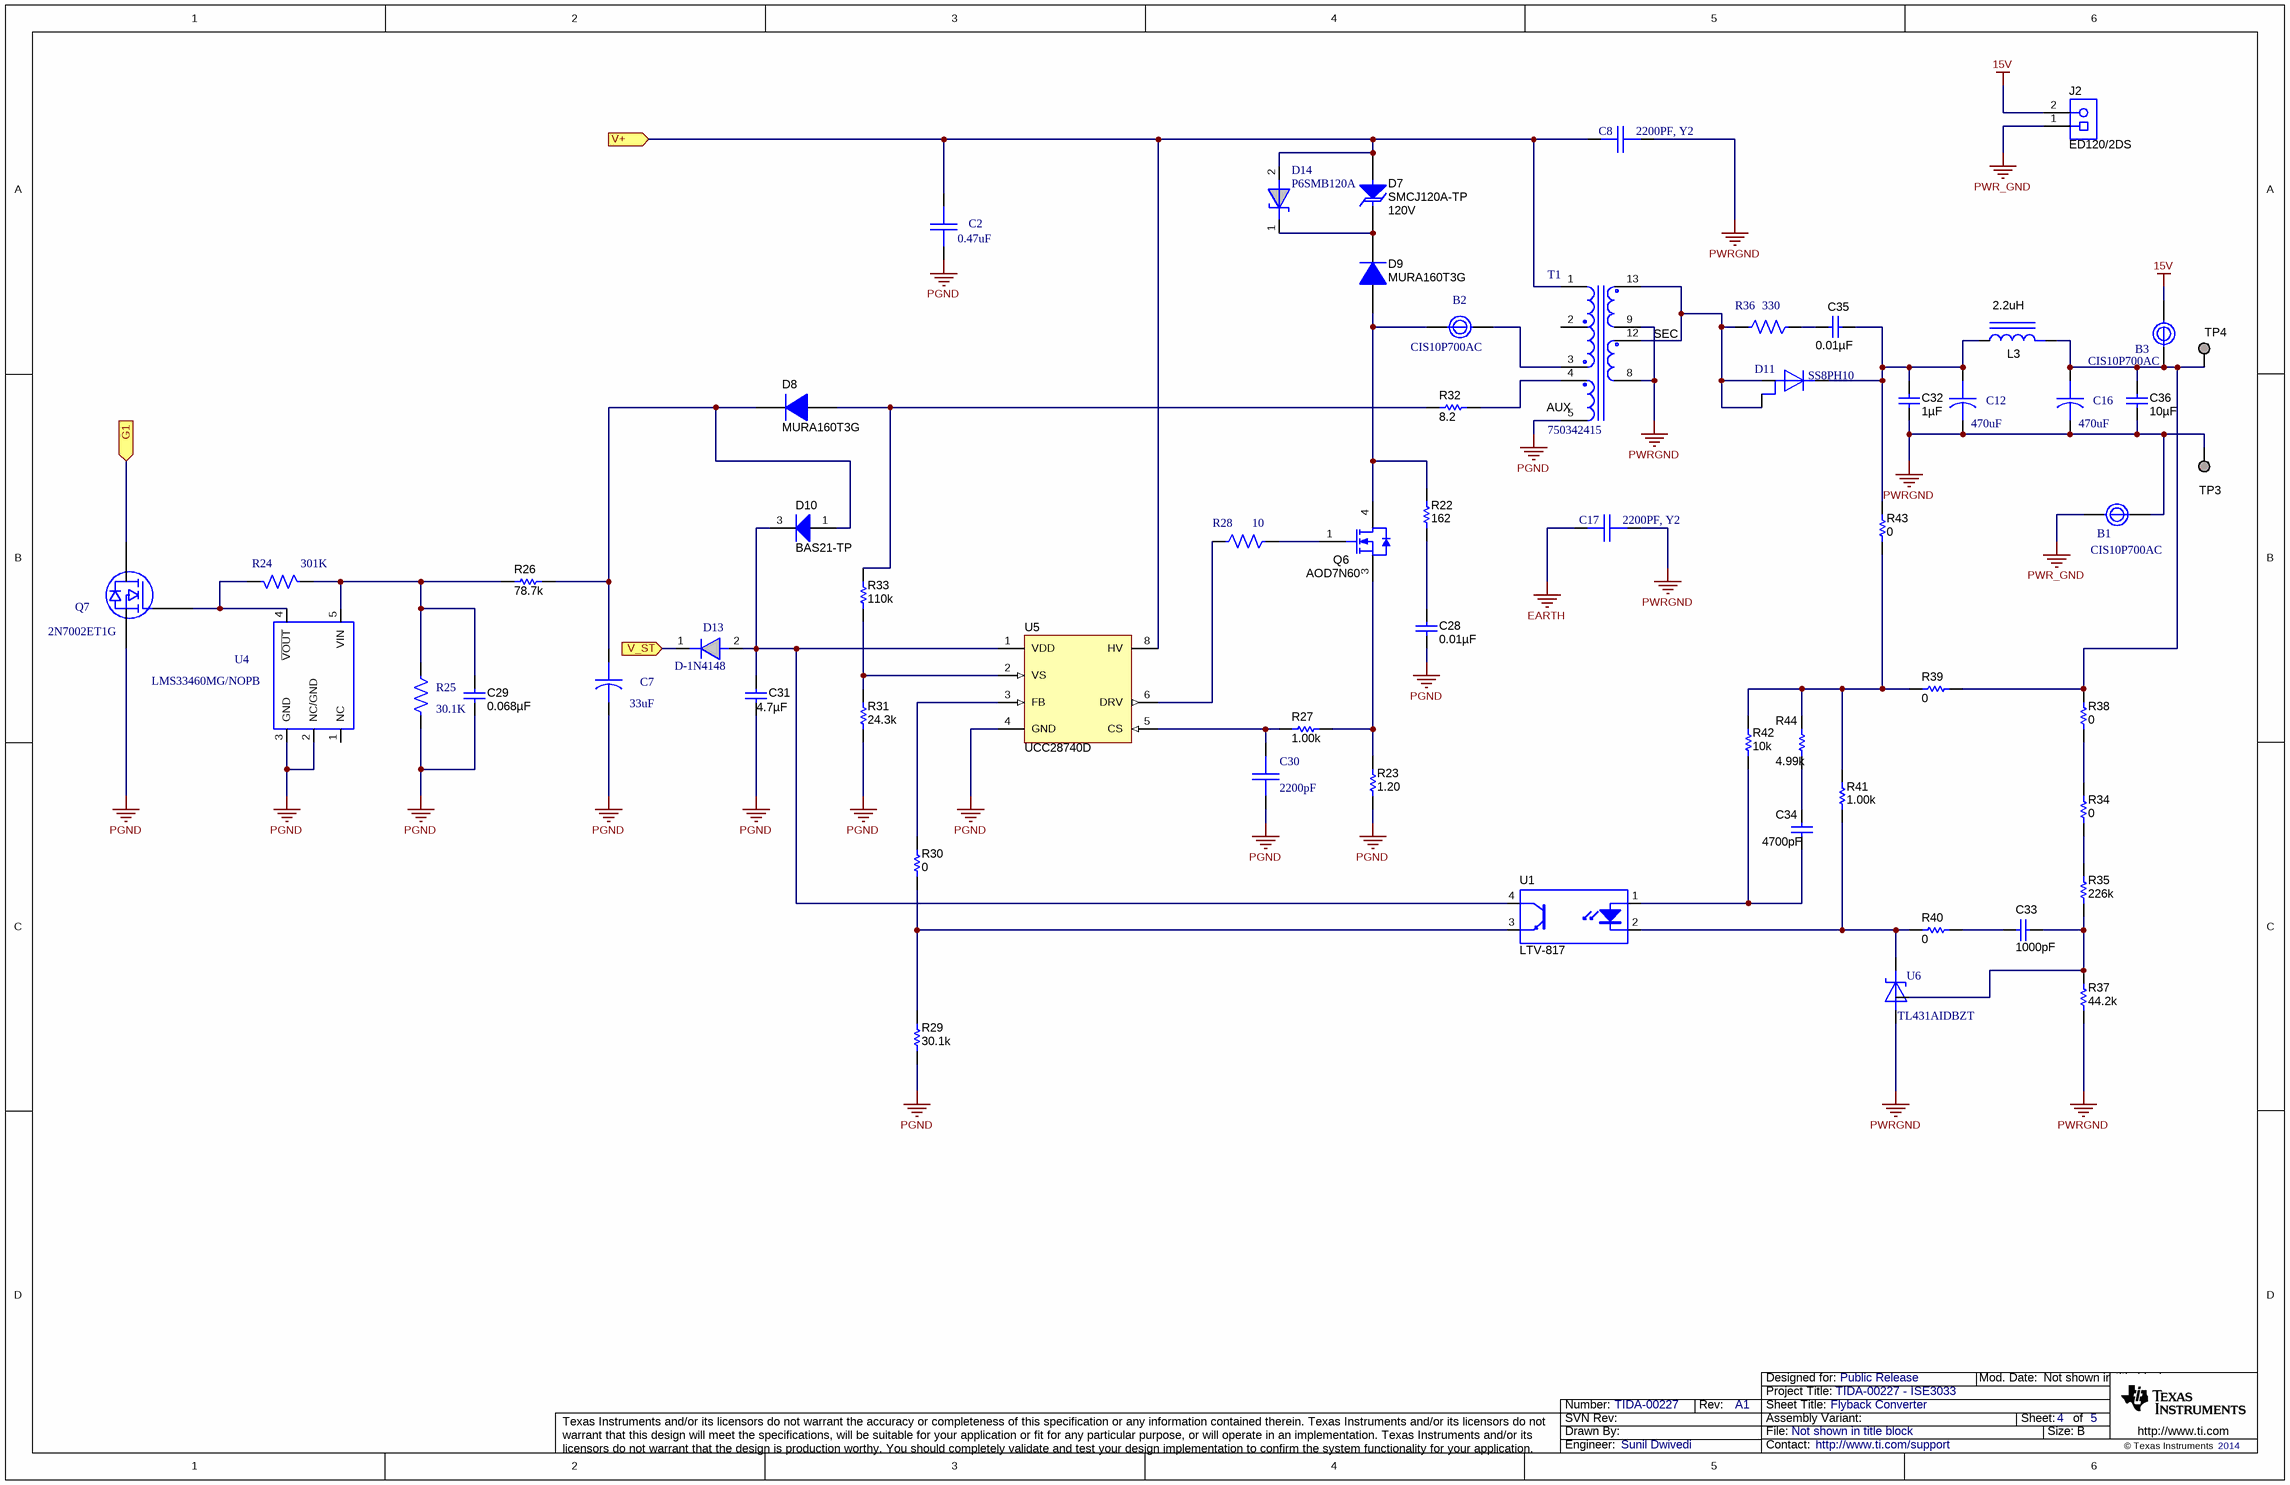
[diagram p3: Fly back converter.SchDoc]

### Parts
B1  CIS10P700AC  [0603]
B2  CIS10P700AC  [0603]
B3  CIS10P700AC  [0603]
C2  value 0.47uF  [CAP_591MIL]  (hidden comment: R46KI347050P1M)
C7  value 33uF  [CAP_ZL-6.3MM]  (hidden comment: CAP_ZL_6.3MM_SERIES)
C8  value 2200PF, Y2  [CAP_DISK_8.4MM]  (hidden comment: VY2222M35Y5US63V7)
C12  value 470uF  [CAP_ALUM-10MM]  (hidden comment: CAP_EKZE_10MM_SERIES)
C16  value 470uF  [CAP_ALUM-10MM]  (hidden comment: CAP_EKZE_10MM_SERIES)
C17  value 2200PF, Y2  [CAP_DISK_8.4MM]  (hidden comment: VY2222M35Y5US63V7)
C28  ValueDisplayed: 0.01µF  [1210]  (hidden comment: GRM32QR73A103KW01L)
C29  ValueDisplayed: 0.068µF  [0603]  (hidden comment: GRM188R71H683KA93D)
C30  value 2200pF  [C603]  (hidden comment: C603)
C31  ValueDisplayed: 4.7µF  [0805_HV]  (hidden comment: C2012X5R1H475K125AB)
C32  ValueDisplayed: 1µF  [0805_HV]  (hidden comment: 08053D105KAT2A)
C33  ValueDisplayed: 1000pF  [0603]  (hidden comment: 06031C102JAT2A)
C34  ValueDisplayed: 4700pF  [0603]  (hidden comment: 06031C472JAT2A)
C35  ValueDisplayed: 0.01µF  [1210]  (hidden comment: GRM32QR73A103KW01L)
C36  ValueDisplayed: 10µF  [0603]  (hidden comment: GRM188R61E106MA73)
D7  SMCJ120A-TP  value 120V  [SMC]
D8  MURA160T3G  [SMA]
D9  MURA160T3G  [SMA]
D10  BAS21-TP  [SOT-23]
D11  value SS8PH10  [TO-277[SMPC]]  (hidden comment: D-S4P_SERIES)
D13  D-1N4148  [D_SOD123]
D14  P6SMB120A  [SMB]
J2  ED120/2DS  [CONN_ED120-2DS]
L3  2.2uH  [IND_200_MIL]
Q6  AOD7N60  [DPAK]
Q7  value 2N7002ET1G  [SOT-23]  (hidden comment: TR-2N7002)
R22  value 162  [2512M]  (hidden comment: CRCW2512162RFKEGHP)
R23  value 1.20  [2512M]  (hidden comment: ERJ-1TRQF1R2U)
R24  value 301K  [r603]  (hidden comment: R603)
R25  value 30.1K  [r603]  (hidden comment: R603)
R26  value 78.7k  [0603]  (hidden comment: CRCW060378K7FKEA)
R27  value 1.00k  [0603]  (hidden comment: CRCW06031K00FKEA)
R28  value 10  [r0805]  (hidden comment: R0805_1%)
R29  value 30.1k  [0603]  (hidden comment: CRCW060330K1FKEA)
R30  value 0  [0603]  (hidden comment: CRCW06030000Z0EA)
R31  value 24.3k  [0603]  (hidden comment: CRCW060324K3FKEA)
R32  value 8.2  [2010M]  (hidden comment: CRCW20108R20JNEF)
R33  value 110k  [0603]  (hidden comment: CRCW0603110KJNEA)
R34  value 0  [0603]  (hidden comment: CRCW06030000Z0EA)
R35  value 226k  [0603]  (hidden comment: CRCW0603226KFKEA)
R36  value 330  [R2512]  (hidden comment: R2512)
R37  value 44.2k  [0603]  (hidden comment: CRCW060344K2FKEA)
R38  value 0  [0603]  (hidden comment: CRCW06030000Z0EA)
R39  value 0  [0603]  (hidden comment: CRCW06030000Z0EA)
R40  value 0  [0603]  (hidden comment: CRCW06030000Z0EA)
R41  value 1.00k  [0603]  (hidden comment: CRCW06031K00FKEA)
R42  value 10k  [0603]  (hidden comment: CRCW060310K0JNEA)
R43  value 0  [0603]  (hidden comment: CRCW06030000Z0EA)
R44  value 4.99k  [0603]  (hidden comment: CRCW06034K99FKEA)
T1  750342415  [WE_750342415]
TP3  TESTPOINT  [TESTPOINT]  (value not drawn)  (no BOM)
TP4  TESTPOINT  [TESTPOINT]  (value not drawn)  (no BOM)
U1  LTV-817  [DIP762W60P254L460H350Q4B]
U4  value LMS33460MG/NOPB  [SC-70-5]  (hidden comment: LMS33460)
U5  UCC28740D  [D0007A_N]
U6  value TL431AIDBZT  [SOT-23]  (hidden comment: TL431AIDBZ)

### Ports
G1, V+, V_ST

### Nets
15V: B3.2 J2.2
EARTH: C17.1
PGND: C2.1 C7.2 C28.2 C29.2 C30.1 C31.1 Q7.2(S) R23.2 R25.2 R29.1 R31.1 T1.5 U4.2(NC/GND) U4.3(GND) U5.4(GND)
PWR_GND: B1.2 J2.1
PWRGND: B1.1 C8.2 C12.2 C16.2 C17.2 C32.2 C36.2 R37.1 T1.8 T1.9 TP3.1 U6.3(A)
NetB2_1: B2.1 D9.2(A) Q6.4(D) R22.2
NetB2_2: B2.2 T1.3
NetB3_1: B3.1 C16.1 C36.1 L3.2 R38.2 R39.2 TP4.1
NetC1_1: D13.1(C) ; port V_ST
NetC2_2: C2.2 C8.1 D7.2(A) D14.2(A) T1.1 U5.8(HV) ; port V+
NetC7_1: C7.1 D8.1(K) D10.1(A) R26.2
NetC12_1: C12.1 C32.1 C35.2 D11.3(C) L3.1 R43.2
NetC28_1: C28.1 R22.1
NetC29_1: C29.1 R24.1 R25.1 R26.1 U4.5(VIN)
NetC30_2: C30.2 R27.1 U5.5(CS)
NetC31_2: C31.2 D10.3(K) D13.2(A) U1.4(C) U5.1(VDD)
NetC33_1: C33.1 R35.1 R37.2 U6.2(REF)
NetC33_2: C33.2 R40.2
NetC34_1: C34.1 R42.1 U1.1(A)
NetC34_2: C34.2 R44.2
NetC35_1: C35.1 R36.2
NetD7_1: D7.1(K) D9.1(K) D14.1(C)
NetD8_2: D8.2(A) R32.1 R33.2
NetD11_1: D11.1 D11.2(A) R36.1 T1.12 T1.13
NetQ2_1: Q7.3(D) ; port G1
NetQ6_1: Q6.1(G) R28.2
NetQ6_3: Q6.3(S) R23.1 R27.2
NetQ7_1: Q7.1(G) R24.2 U4.4(~{VOUT})
NetR28_1: R28.1 U5.6(DRV)
NetR29_2: R29.2 R30.1 U1.3(E)
NetR30_2: R30.2 U5.3(FB)
NetR31_2: R31.2 R33.1 U5.2(VS)
NetR32_2: R32.2 T1.4
NetR34_1: R34.1 R35.2
NetR34_2: R34.2 R38.1
NetR39_1: R39.1 R41.2 R42.2 R43.1 R44.1
NetR40_1: R40.1 R41.1 U1.2(K) U6.1(C)

Not connected (* = marked no-connect by the designer): T1 2; U4 1(NC)

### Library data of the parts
B1-B3 = BEAD-BLM18AG_SERIES: FERRITE CHIP 70 OHM 4000MA 0603; Manufacturer: Samsung; Second Source: C:\program files\p-cad 2004\pcad_pdf's\Bead BML SERIES.pdf; Reference: \\vette02\pmp_pcb\pcad_pdf's\Bead BML SERIES.pdf; Area: 5.87 mm; Value: 70ohm
C2 = CAP_ECQU2A104XL: as C4 on sheet Boost converter
C7 = CAP_ZL_6.3MM_SERIES: as C1 on sheet Boost converter
C8 C17 = CAP_DISK_440_[8.4MM]: as C13 on sheet Boost converter
C12 C16 = CAP_EKZE_10MM_SERIES: CAP ALUM 470UF 35V 20% RADIAL; Manufacturer: Panasonic; Part_Number: EEU-FM1V471; Part_Number: Part Number; Area: 96.42 mm; Second Source: C:\program files\p-cad 2004\pcad_pdf's\ekze_cap.pdf; Reference: \\vette02\pmp_pcb\pcad_pdf's\ekze_cap.pdf
C28 C35 = GRM32QR73A103KW01L: as C5 on sheet Boost converter
C29 = GRM188R71H683KA93D: as C18 on sheet Boost converter
C30 = C603: as C20 on sheet Boost converter
C31 = C2012X5R1H475K125AB: CAP, CERM, 4.7uF, 50V, +/-10%, X5R, 0805; Manufacturer: TDK; Polarized: N; CompType: Capacitor; U/M: EA; Cap_F: 0.0000047; Tolerance_%: 10; Value1: Unknown; VDC_V: 50; TaMin_C: -55; TaMax_C: 85; Cap_Case: 0805
C32 = 08053D105KAT2A: CAP, CERM, 1uF, 25V, +/-10%, X5R, 0805; Manufacturer: AVX; Polarized: N; CompType: Capacitor; U/M: EA; Cap_F: 0.000001; Tolerance_%: 10; ESR_Ohm: 0.012; Value1: 0.012 ohm; VDC_V: 25; TaMin_C: -55; TaMax_C: 85; Cap_Case: 0805
C33 = 06031C102JAT2A: CAP, CERM, 1000pF, 100V, +/-5%, X7R, 0603; Manufacturer: AVX; Polarized: N; CompType: Capacitor; U/M: EA; Cap_F: 0.000000001; Tolerance_%: 5; ESR_Ohm: 0.276; Value1: 0.276 ohm; VDC_V: 100; TaMin_C: -55; TaMax_C: 125
C34 = 06031C472JAT2A: CAP, CERM, 4700pF, 100V, +/-5%, X7R, 0603; Manufacturer: AVX; Polarized: N; CompType: Capacitor; U/M: EA; Cap_F: 0.0000000047; Tolerance_%: 5; ESR_Ohm: 0.136; Value1: 0.136 ohm; VDC_V: 100; TaMin_C: -55; TaMax_C: 125
C36 = GRM188R61E106MA73: CAP, CERM, 10uF, 25V, +/-20%, X5R, 0603; Manufacturer: MuRata; Polarized: N; CompType: Capacitor; U/M: EA; Cap_F: 0.00001; Tolerance_%: 20; Value1: Unknown; VDC_V: 25; TaMin_C: -55; TaMax_C: 85
D7 = SMCJ120A-TP: Diode, TVS, Uni, 120V, 1500W, SMC; Manufacturer: Micro Commercial Components; U/M: EA; Power_W: 1500; Vr_V: 120
D8 D9 = MURA160T3G: as D6 on sheet Boost converter
D10 = BAS21-TP: Diode, P-N, 200V, 200A, SOT-23; Manufacturer: Micro Commercial Components; U/M: EA; Vf_V: 1.25; Value2: 1.25V; Io_A: 200; TJmax_C: 150; RJC_CperW: 430
D11 = D-S4P_SERIES: Diode Schottky, 8A, 100V; PartNumber: SS8PH10-M3/86A; Manufacturer: Vishay; Area: 73600; Second Source: C:\program files\p-cad 2004\pcad_pdf's\s4pm[1].pdf; Reference: \\vette02\pmp_pcb\pcad_pdf's\s4pm[1].pdf
D13 = D-1N4148: Diode, Signal, 300-mA, 75-V, 350-mW; PartNumber: 1N4148W-7-F; Manufacturer: Diodes; Area: 13300; Value: 1N4148W-7-F
D14 = D-P6SMBXXXA: TVS DIODE 102VWM 165VC SMD; Manufacturer: General; Area: 53200
J2 = ED120/2DS: TERMINAL BLOCK 5.08MM VERT 2POS, TH; Manufacturer: On-Shore Technology; SymbolCreator: a0412235; U/M: EA
L3 = IND_RFB0807_SERIES: INDUCTOR 2.2UH 4.1A RADIAL; Manufacturer: Taiyo Yuden; Part_Number: LHL08TB2R2M; Area: 113411; Type: PD2 744
Q6 = AOD7N60: MOSFET, N-CH, 600V, 7A, DPAK; Manufacturer: AOS; Alternate Manufacturer: None; U/M: EA; ChType: N; VdsMax_V: 600; Value1: ? ohm; Value2: 19.3 nC; QgTyp_nC: 19.3; Vgs_V: 30; IdsMax_A: 7
Q7 = TR-2N7002: as Q4 on sheet Boost converter
R22 = CRCW2512332RFKEG: RES 162 OHM 1.5W 1% 2512 SMD; Manufacturer: Vishay-Dale; CompType: Resistor; Value_Code: 162R; Tolerance_%: 1; EIA_Code: E96; U/M: EA
R23 = ERJ-1TRQF1R2U: RES, 1.20 ohm, 1%, 1W, 2512; Manufacturer: Panasonic; CompType: Resistor; Res_ohm: 1.2; Value_Code: 1R20; Tolerance_%: 1; TempCo: 100 ppm/C; U/M: EA
R24 = R603: RES 301K OHM 1/10W 1% 0603 SMD; Part_Number: RC0603FR-07301KL; Manufacturer: Yageo; Area: 5650
R25 = R603: as R20 on sheet Boost converter
R26 = CRCW060378K7FKEA: RES, 78.7k ohm, 1%, 0.1W, 0603; Manufacturer: Vishay-Dale; CompType: Resistor; Res_ohm: 78700; Value_Code: 78k7; Tolerance_%: 1; Power_W: 0.1; VDC_V: 75; TempCo: 100 ppm/C; EIA_Code: E96; U/M: EA
R27 R41 = CRCW06031K00FKEA: RES, 1.00k ohm, 1%, 0.1W, 0603; Manufacturer: Vishay-Dale; CompType: Resistor; Res_ohm: 1000; Value_Code: 1k00; Tolerance_%: 1; Power_W: 0.1; VDC_V: 75; TempCo: 100 ppm/C; EIA_Code: E96; U/M: EA
R28 = R0805_1%: RES 10.0 OHM 1/8W 1% 0805 SMD; Part_Number: RC0805FR-0710RL; Manufacturer: Yageo; Area: 15,300
R29 = CRCW060330K1FKEA: RES, 30.1k ohm, 1%, 0.1W, 0603; Manufacturer: Vishay-Dale; CompType: Resistor; Res_ohm: 30100; Value_Code: 30k1; Tolerance_%: 1; Power_W: 0.1; VDC_V: 75; TempCo: 100 ppm/C; EIA_Code: E96; U/M: EA
R30 R34 R38-R40 R43 = CRCW06030000Z0EA: RES, 0 ohm, 5%, 0.1W, 0603; Manufacturer: Vishay-Dale; CompType: Resistor; Value_Code: 0000; Tolerance_%: 5; Power_W: 0.1; VDC_V: 75; TempCo: 200 ppm/C; EIA_Code: E24; U/M: EA
R31 = CRCW060324K3FKEA: RES, 24.3k ohm, 1%, 0.1W, 0603; Manufacturer: Vishay-Dale; CompType: Resistor; Res_ohm: 24300; Value_Code: 24k3; Tolerance_%: 1; Power_W: 0.1; VDC_V: 75; TempCo: 100 ppm/C; EIA_Code: E96; U/M: EA
R32 = CRCW20108R20JNEF: RES, 8.2 ohm, 5%, 0.75W, 2010; Manufacturer: Vishay-Dale; CompType: Resistor; Value_Code: 8R20; Tolerance_%: 5; Power_W: 0.75; VDC_V: 400; TempCo: 200 ppm/C; EIA_Code: E24; U/M: EA
R33 = CRCW0603110KJNEA: RES, 110k ohm, 5%, 0.1W, 0603; Manufacturer: Vishay-Dale; CompType: Resistor; Res_ohm: 110000; Tolerance_%: 5; Power_W: 0.1; VDC_V: 75; TempCo: 200 ppm/C; EIA_Code: E24; U/M: EA
R35 = CRCW0603226KFKEA: RES, 226k ohm, 1%, 0.1W, 0603; Manufacturer: Vishay-Dale; CompType: Resistor; Res_ohm: 226000; Tolerance_%: 1; Power_W: 0.1; VDC_V: 75; TempCo: 100 ppm/C; EIA_Code: E96; U/M: EA
R36 = R2512: as R1 on sheet Boost converter
R37 = CRCW060344K2FKEA: RES, 44.2k ohm, 1%, 0.1W, 0603; Manufacturer: Vishay-Dale; CompType: Resistor; Res_ohm: 44200; Value_Code: 44k2; Tolerance_%: 1; Power_W: 0.1; VDC_V: 75; TempCo: 100 ppm/C; EIA_Code: E96; U/M: EA
R42 = CRCW060310K0JNEA: RES, 10k ohm, 5%, 0.1W, 0603; Manufacturer: Vishay-Dale; CompType: Resistor; Res_ohm: 10000; Value_Code: 10k0; Tolerance_%: 5; Power_W: 0.1; VDC_V: 75; TempCo: 200 ppm/C; EIA_Code: E24; U/M: EA
R44 = CRCW06034K99FKEA: RES, 4.99k ohm, 1%, 0.1W, 0603; Manufacturer: Vishay-Dale; CompType: Resistor; Res_ohm: 4990; Value_Code: 4k99; Tolerance_%: 1; Power_W: 0.1; VDC_V: 75; TempCo: 100 ppm/C; EIA_Code: E96; U/M: EA
T1 = 750342415: TRANSFOERMER, 856uH, +/-10%, TH, 14-PIN; Manufacturer: WURTH ELEKTRONIK; CompType: TRANSFORMER; SymbolCreator: x0199378
TP3 TP4 = TESTPOINT: as TP1 on sheet Boost converter
U1 = LTV-817: Opto-Isolator, 1 Channel, TH; Manufacturer: Lite-On; CompType: OPTOCOUPLER; U/M: EA
U4 = LMS33460: as U3 on sheet Boost converter
U5 = UCC28740D: Constant-Voltage, Constant-Current Flyback Controller Using Opto-Coupler Feedback, D0007A; Alternate Manufacturer: None; Manufacturer: Texas Instruments; SymbolCreator: a0412235; CompType: IC; U/M: EA
U6 = TL431AIDBZ: IC VREF SHUNT PREC ADJ SOT23-3; Manufacturer: TI; Second Source: C:\program files\p-cad 2004\pcad_pdf's\TL431A-B.pdf; Reference: \\vette02\pmp_pcb\pcad_pdf's\TL431A-B.pdf; Area: 16384

## Sheet Hardware.SchDoc: Hardware
size 431 x 279 mm; Date: Not shown in title block; ApprovedBy: Not shown in title block; CheckedBy: Not shown in title block; Author: Not shown in title block; CompanyName: Not shown in title block; Engineer: Not shown in title block; Organization: Not shown in title block; Address1: Not shown in title block; Address2: Not shown in title block; Address3: Not shown in title block; Address4: Not shown in title block; DocumentNumber: 5; Revision: Use project parameter SCH_Rev; SheetNumber: 5; SheetTotal: 5; PageSetup: Record=PageOptions|CenterHorizontal=True|CenterVertical=True|PrintScale=1.00|XCorrection=1.00|YCorrection=1.00|PrintKind=0|BorderSize=5000000|LeftOffset=0|BottomOffset=0|Orientation=2|PaperLength=1000|PaperWidth=1000|Scale=100|PaperSource=15|PrintQuality=600|MediaType=1|DitherType=10|PaperKind=Letter|PrintScaleMode=1
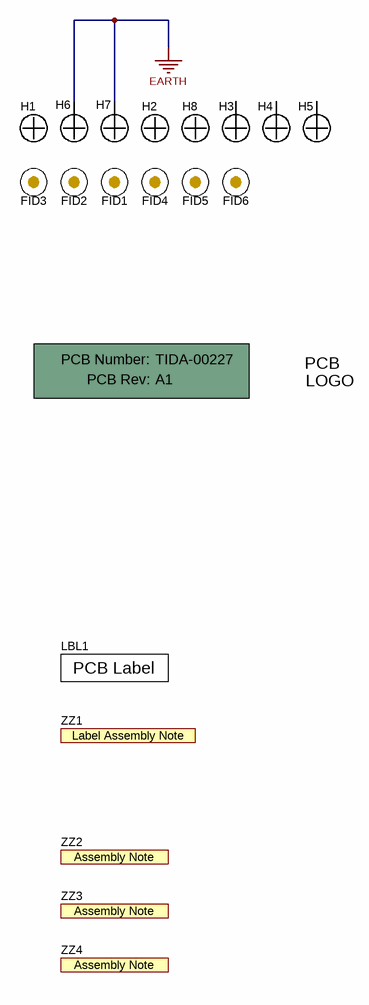
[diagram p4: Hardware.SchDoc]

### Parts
!PCB1  (no value)  (mechanical)
FID1  Fiducial  [Fiducial10-20]  (value not drawn)
FID2  Fiducial  [Fiducial10-20]  (value not drawn)
FID3  Fiducial  [Fiducial10-20]  (value not drawn)
FID4  Fiducial  [Fiducial10-20]  (value not drawn)
FID5  Fiducial  [Fiducial10-20]  (value not drawn)
FID6  Fiducial  [Fiducial10-20]  (value not drawn)
H1  (no value)  [MH3.2_H5_W6_KO8_STARHEAD]
H2  (no value)  [MH3.2_H5_W6_KO8_STARHEAD]
H3  (no value)  [NY PMS 440 0025 PH]
H4  (no value)  [NY PMS 440 0025 PH]
H5  (no value)  [NY PMS 440 0025 PH]
H6  (no value)  [NY PMS 440 0025 PH]
H7  (no value)  [NY PMS 440 0025 PH]
H8  (no value)  [MH3.2_H5_W6_KO8_STARHEAD]
LBL1  (no value)  [Label_650x200]
Logo1  (no value)  [TI_Stacked_SolderMask_Small]  (no BOM)
ZZ1  (no value)  [AssemblyNoteLabel]  (no BOM)
ZZ2  (no value)  [AssemblyNote]  (no BOM)
ZZ3  (no value)  [AssemblyNote]  (no BOM)
ZZ4  (no value)  [AssemblyNote]  (no BOM)

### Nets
EARTH: H6.1 H7.1

Not connected (* = marked no-connect by the designer): H3 1; H4 1; H5 1

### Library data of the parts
!PCB1 = PCB: Printed Circuit Board; Manufacturer: Any; PartNumber: TIDA-00227; Part_Number: Part Number; SymbolCreator: a0412235
FID1-FID6 = Fiducial: Fiducial mark.  There is nothing to buy or mount.; Part_Number: Part Number; SymbolCreator: codlsc
H1-H8 = NY PMS 440 0025 PH: Mounting Hole M3 3.5mm; Manufacturer: STD; CompType: Hardware; U/M: EA
LBL1 = THT-14-423-10: Thermal Transfer Printable Labels, 0.650" W x 0.200" H - 10,000 per roll; Manufacturer: Brady; Part_Number: Part Number; SymbolCreator: a0412235; CompType: Label; Note: Size: 0.65" x 0.20 "
Logo1 = TI_Logo: Texas Instrument Corporate Signature; Part_Number: Part Number; SymbolCreator: codlsc
ZZ1 = AssemblyNoteLabel: This Assembly Note is for PCB labels only; Part_Number: Part Number; SymbolCreator: a0412235
ZZ2 = AssemblyNote: These assemblies are ESD sensitive, ESD precautions shall be observed.; Part_Number: Part Number; SymbolCreator: codlsc
ZZ3 = AssemblyNote: These assemblies must be clean and free from flux and all contaminants. Use of no clean flux is not acceptable.; Part_Number: Part Number; SymbolCreator: codlsc
ZZ4 = AssemblyNote: These assemblies must comply with workmanship standards IPC-A-610 Class 2, unless otherwise specified.; Part_Number: Part Number; SymbolCreator: codlsc

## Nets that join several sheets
EARTH: Boost converter (6 pins), Fly back converter (C17.1), Hardware (H6.1 H7.1)
PGND: Boost converter (28 pins), Fly back converter (15 pins)
NetC1_1: Boost converter (8 pins), Fly back converter (D13.1)
NetC2_2: Boost converter (6 pins), Fly back converter (6 pins)
NetQ2_1: Boost converter (Q2.1 Q3.1 R9.1), Fly back converter (Q7.3)

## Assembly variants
001: not fitted C5 C10 C11 C21 C25 C26 C28 C29 C35 D7 Q3 R1 R19 R22 R36 R39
